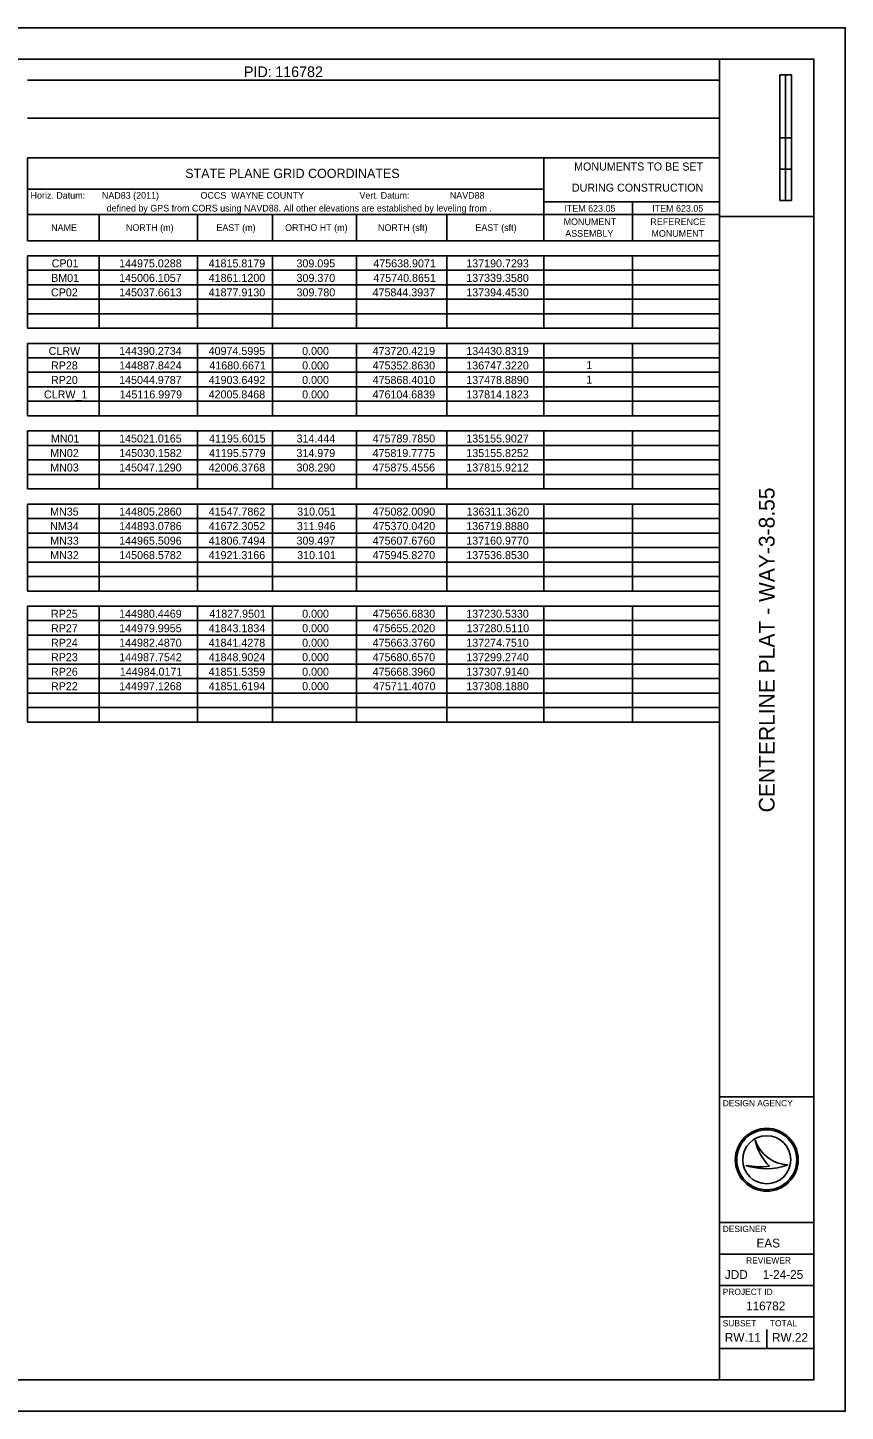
# Model space of a CAD drawing. Extents: x 0 to 34, y 0 to 22.
# Drawn here: x 21 to 34, y 0 to 22 of the extents above; entities that cross this region are included whole.
import ezdxf

# ---------------------------------------------------------------- set-up
doc = ezdxf.new("R2010")
doc.units = 0
for name, color, linetype in [('SH_Border', 7, 'Continuous'), ('SH_Cut_Line', 7, 'Continuous'), ('SH_Data', 7, 'Continuous'), ('SH_Text', 7, 'Continuous')]:
    doc.layers.add(name, color=color, linetype=linetype)

msp = doc.modelspace()

# ---------------------------------------------------------------- linework, layer by layer
at = {"layer": 'SH_Border'}
for p, q in [((32, 0.5), (32, 21.5)), ((32, 19), (33.5, 19)), ((32, 5), (33.5, 5)), ((32, 3), (33.5, 3)), ((32, 2.5), (33.5, 2.5)), ((32, 2), (33.5, 2)), ((32, 1.5), (33.5, 1.5)), ((32, 1), (33.5, 1))]:
    msp.add_line(p, q, dxfattribs=at)
msp.add_lwpolyline([(1.5, 21.5), (33.5, 21.5), (33.5, 0.5), (1.5, 0.5)], close=True, dxfattribs=at)
at = {"layer": 'SH_Cut_Line'}
msp.add_lwpolyline([(0, 0), (34, 0), (34, 22), (0, 22)], close=True, dxfattribs=at)
at = {"layer": 'SH_Data'}
for p, q in [((32.957, 19.25), (32.957, 21.25)), ((33.144, 21.25), (32.957, 21.25)), ((32.957, 20.25), (32.957, 21.25)), ((32.957, 21.25), (33.05, 21.25)), ((33.05, 21.25), (33.051, 21.25)), ((33.051, 21.25), (33.051, 20.25)), ((33.144, 21.25), (33.144, 19.25)), ((33.051, 20.25), (32.957, 20.25)), ((33.143, 20.25), (33.05, 20.25)), ((33.05, 20.25), (33.05, 19.75)), ((33.143, 19.75), (33.143, 20.25)), ((33.05, 19.75), (32.957, 19.75)), ((32.957, 19.75), (32.957, 19.25)), ((33.05, 19.75), (33.143, 19.75)), ((33.05, 19.25), (33.05, 19.75)), ((33.144, 19.25), (32.957, 19.25)), ((32.957, 19.25), (33.05, 19.25)), ((32.567, 4.31), (32.567, 4.31)), ((32.75, 4), (32.75, 4)), ((32.417, 3.91), (32.417, 3.91)), ((33.087, 3.919), (33.087, 3.919)), ((32.75, 1), (32.75, 1.3))]:
    msp.add_line(p, q, dxfattribs=at)
for radius in [0.5, 0.477, 0.477, 0.382]:
    msp.add_circle((32.75, 4), radius, dxfattribs=at)
for centre, radius, start, end in [((33.116, 4.498), 0.58, 198.9257, 198.9319), ((33.347, 4.47), 0.796, 191.6379, 191.6421), ((33.116, 4.498), 0.58, 198.9319, 267.1657), ((33.347, 4.47), 0.796, 191.6421, 226.0947), ((32.739, 4.87), 1.013, 251.4576, 290.0832), ((32.648, 5.154), 1.266, 259.4964, 259.4995), ((32.739, 4.87), 1.013, 251.4527, 251.4576), ((32.648, 5.154), 1.266, 259.4995, 276.6672)]:
    msp.add_arc(centre, radius, start, end, dxfattribs=at)
at = {"layer": 'SH_Text'}
for p, q in [((20.997, 21.168), (22.132, 21.168)), ((22.132, 21.168), (32, 21.168)), ((32, 21.168), (32, 19.932)), ((20.997, 20.559), (22.132, 20.559)), ((22.132, 20.559), (32, 20.559)), ((20.997, 19.932), (22.132, 19.932)), ((20.997, 19.932), (20.997, 19.028)), ((22.132, 19.932), (32, 19.932)), ((29.205, 19.932), (29.205, 19.028)), ((32, 19.932), (32, 19.028)), ((20.997, 19.434), (22.132, 19.434)), ((22.132, 19.434), (29.205, 19.434)), ((29.205, 19.231), (32, 19.231)), ((30.617, 19.231), (30.617, 19.028)), ((20.997, 19.028), (22.132, 19.028)), ((20.997, 19.028), (20.997, 18.613)), ((22.132, 19.028), (32, 19.028)), ((22.132, 19.028), (22.132, 18.613)), ((23.699, 19.028), (23.699, 18.613)), ((24.889, 19.028), (24.889, 18.613)), ((26.226, 19.028), (26.226, 18.613)), ((27.665, 19.028), (27.665, 18.613)), ((29.205, 19.028), (29.205, 18.613)), ((30.617, 19.028), (30.617, 18.613)), ((32, 19.028), (32, 17.451)), ((20.997, 18.613), (22.132, 18.613)), ((22.132, 18.613), (32, 18.613)), ((20.997, 18.373), (22.132, 18.373)), ((20.997, 18.373), (20.997, 17.451)), ((22.132, 18.373), (32, 18.373)), ((22.132, 18.373), (22.132, 17.451)), ((23.699, 18.373), (23.699, 17.451)), ((24.889, 18.373), (24.889, 17.451)), ((26.226, 18.373), (26.226, 17.451)), ((27.665, 18.373), (27.665, 17.451)), ((29.205, 18.373), (29.205, 17.451)), ((30.617, 18.373), (30.617, 17.451)), ((20.997, 18.143), (22.132, 18.143)), ((22.132, 18.143), (32, 18.143)), ((20.997, 17.912), (22.132, 17.912)), ((22.132, 17.912), (32, 17.912)), ((20.997, 17.682), (22.132, 17.682)), ((22.132, 17.682), (32, 17.682)), ((20.997, 17.451), (22.132, 17.451)), ((20.997, 17.451), (20.997, 17.221)), ((22.132, 17.451), (32, 17.451)), ((22.132, 17.451), (22.132, 17.221)), ((23.699, 17.451), (23.699, 17.221)), ((24.889, 17.451), (24.889, 17.221)), ((26.226, 17.451), (26.226, 17.221)), ((27.665, 17.451), (27.665, 17.221)), ((29.205, 17.451), (29.205, 17.221)), ((30.617, 17.451), (30.617, 17.221)), ((32, 17.451), (32, 16.981)), ((20.997, 17.221), (22.132, 17.221)), ((22.132, 17.221), (32, 17.221)), ((20.997, 16.981), (22.132, 16.981)), ((20.997, 16.981), (20.997, 15.828)), ((22.132, 16.981), (32, 16.981)), ((22.132, 16.981), (22.132, 15.828)), ((23.699, 16.981), (23.699, 15.828)), ((24.889, 16.981), (24.889, 15.828)), ((26.226, 16.981), (26.226, 15.828)), ((27.665, 16.981), (27.665, 15.828)), ((29.205, 16.981), (29.205, 15.828)), ((30.617, 16.981), (30.617, 15.828)), ((32, 16.981), (32, 13.504)), ((20.997, 16.75), (22.132, 16.75)), ((22.132, 16.75), (32, 16.75)), ((20.997, 16.52), (22.132, 16.52)), ((22.132, 16.52), (32, 16.52)), ((20.997, 16.289), (22.132, 16.289)), ((22.132, 16.289), (32, 16.289)), ((20.997, 16.059), (22.132, 16.059)), ((22.132, 16.059), (32, 16.059)), ((20.997, 15.828), (22.132, 15.828)), ((22.132, 15.828), (32, 15.828)), ((20.997, 15.588), (22.132, 15.588)), ((20.997, 15.588), (20.997, 14.666)), ((22.132, 15.588), (32, 15.588)), ((22.132, 15.588), (22.132, 14.666)), ((23.699, 15.588), (23.699, 14.666)), ((24.889, 15.588), (24.889, 14.666)), ((26.226, 15.588), (26.226, 14.666)), ((27.665, 15.588), (27.665, 14.666)), ((29.205, 15.588), (29.205, 14.666)), ((30.617, 15.588), (30.617, 14.666)), ((20.997, 15.358), (22.132, 15.358)), ((22.132, 15.358), (32, 15.358)), ((20.997, 15.127), (22.132, 15.127)), ((22.132, 15.127), (32, 15.127)), ((20.997, 14.896), (22.132, 14.896)), ((22.132, 14.896), (32, 14.896)), ((20.997, 14.666), (22.132, 14.666)), ((22.132, 14.666), (32, 14.666)), ((20.997, 14.426), (22.132, 14.426)), ((20.997, 14.426), (20.997, 13.504)), ((22.132, 14.426), (32, 14.426)), ((22.132, 14.426), (22.132, 13.504)), ((23.699, 14.426), (23.699, 13.504)), ((24.889, 14.426), (24.889, 13.504)), ((26.226, 14.426), (26.226, 13.504)), ((27.665, 14.426), (27.665, 13.504)), ((29.205, 14.426), (29.205, 13.504)), ((30.617, 14.426), (30.617, 13.504)), ((20.997, 14.195), (22.132, 14.195)), ((22.132, 14.195), (32, 14.195)), ((20.997, 13.965), (22.132, 13.965)), ((22.132, 13.965), (32, 13.965)), ((20.997, 13.734), (22.132, 13.734)), ((22.132, 13.734), (32, 13.734)), ((20.997, 13.504), (22.132, 13.504)), ((20.997, 13.504), (20.997, 13.043)), ((22.132, 13.504), (32, 13.504)), ((22.132, 13.504), (22.132, 13.043)), ((23.699, 13.504), (23.699, 13.043)), ((24.889, 13.504), (24.889, 13.043)), ((26.226, 13.504), (26.226, 13.043)), ((27.665, 13.504), (27.665, 13.043)), ((29.205, 13.504), (29.205, 13.043)), ((30.617, 13.504), (30.617, 13.043)), ((32, 13.504), (32, 12.803)), ((20.997, 13.273), (22.132, 13.273)), ((22.132, 13.273), (32, 13.273)), ((20.997, 13.043), (22.132, 13.043)), ((22.132, 13.043), (32, 13.043)), ((20.997, 12.803), (22.132, 12.803)), ((20.997, 12.803), (20.997, 10.958)), ((22.132, 12.803), (32, 12.803)), ((22.132, 12.803), (22.132, 10.958)), ((23.699, 12.803), (23.699, 10.958)), ((24.889, 12.803), (24.889, 10.958)), ((26.226, 12.803), (26.226, 10.958)), ((27.665, 12.803), (27.665, 10.958)), ((29.205, 12.803), (29.205, 10.958)), ((30.617, 12.803), (30.617, 10.958)), ((32, 12.803), (32, 10.958)), ((20.997, 12.572), (22.132, 12.572)), ((22.132, 12.572), (32, 12.572)), ((20.997, 12.342), (22.132, 12.342)), ((22.132, 12.342), (32, 12.342)), ((20.997, 12.111), (22.132, 12.111)), ((22.132, 12.111), (32, 12.111)), ((20.997, 11.881), (22.132, 11.881)), ((22.132, 11.881), (32, 11.881)), ((20.997, 11.65), (22.132, 11.65)), ((22.132, 11.65), (32, 11.65)), ((20.997, 11.419), (22.132, 11.419)), ((22.132, 11.419), (32, 11.419)), ((20.997, 11.189), (22.132, 11.189)), ((22.132, 11.189), (32, 11.189)), ((20.997, 10.958), (22.132, 10.958)), ((22.132, 10.958), (32, 10.958))]:
    msp.add_line(p, q, dxfattribs=at)

# ---------------------------------------------------------------- texts
at = {"layer": 'SH_Data'}
msp.add_text('CENTERLINE PLAT - WAY-3-8.55', height=0.25, rotation=90, dxfattribs=at).set_placement((32.875, 9.524))
for s, height, p in [('DESIGN AGENCY', 0.1, (32.05, 4.85)), ('DESIGNER', 0.1, (32.05, 2.85)), ('EAS', 0.14, (32.587, 2.605)), ('REVIEWER', 0.1, (32.422, 2.35)), ('JDD', 0.14, (32.084, 2.105)), ('1-24-25', 0.14, (32.685, 2.105)), ('PROJECT ID', 0.1, (32.05, 1.85)), ('116782', 0.14, (32.421, 1.605)), ('SUBSET', 0.1, (32.05, 1.35)), ('TOTAL', 0.1, (32.8, 1.35)), ('RW.11', 0.14, (32.084, 1.105)), ('RW.22', 0.14, (32.834, 1.105))]:
    msp.add_text(s, height=height, dxfattribs=at).set_placement(p)
at = {"layer": 'SH_Text'}
for s, height, p in [('PID:', 0.1697, (24.437, 21.214)), ('116782', 0.1697, (24.935, 21.214)), ('  MONUMENTS TO BE SET', 0.12728, (29.592, 19.729)), ('STATE PLANE GRID COORDINATES', 0.14849, (23.503, 19.609)), ('Horiz. Datum:', 0.10606, (21.043, 19.28)), ('NAD83 (2011)', 0.10606, (22.178, 19.28)), ('OCCS  WAYNE COUNTY', 0.10606, (23.746, 19.28)), ('Vert. Datum:', 0.10606, (26.273, 19.28)), ('NAVD88', 0.1061, (27.711, 19.28)), (' DURING CONSTRUCTION', 0.12728, (29.604, 19.393)), (' defined by GPS from CORS using NAVD88. All other elevations are established by leveling from .', 0.10606, (22.214, 19.077)), ('ITEM 623.05', 0.10606, (29.532, 19.074)), ('ITEM 623.05', 0.10606, (30.929, 19.074)), ('MONUMENT ', 0.1061, (29.52, 18.861)), ('REFERENCE ', 0.1061, (30.9, 18.861)), ('NAME', 0.1061, (21.371, 18.768)), ('NORTH (m)', 0.1061, (22.56, 18.768)), ('EAST (m)', 0.1061, (23.998, 18.768)), ('ORTHO HT (m)', 0.10606, (25.091, 18.768)), ('NORTH (sft)', 0.10606, (26.568, 18.768)), ('EAST (sft)', 0.1061, (28.117, 18.768)), ('ASSEMBLY', 0.1061, (29.546, 18.675)), ('MONUMENT', 0.1061, (30.917, 18.675)), ('CP01', 0.1273, (21.379, 18.189)), ('144975.0288', 0.12728, (22.452, 18.189)), ('41815.8179', 0.1273, (23.875, 18.189)), ('309.095', 0.1273, (25.272, 18.189)), ('475638.9071', 0.12728, (26.494, 18.189)), ('137190.7293', 0.12728, (27.972, 18.189)), ('BM01', 0.1273, (21.37, 17.958)), ('145006.1057', 0.12728, (22.452, 17.958)), ('41861.1200', 0.1273, (23.876, 17.958)), ('309.370', 0.1273, (25.273, 17.958)), ('475740.8651', 0.12728, (26.494, 17.958)), ('137339.3580', 0.12728, (27.972, 17.958)), ('CP02', 0.1273, (21.368, 17.728)), ('145037.6613', 0.12728, (22.452, 17.728)), ('41877.9130', 0.1273, (23.876, 17.728)), ('309.780', 0.1273, (25.273, 17.728)), ('475844.3937', 0.12728, (26.482, 17.728)), ('137394.4530', 0.12728, (27.972, 17.728)), ('CLRW', 0.1273, (21.331, 16.796)), ('144390.2734', 0.12728, (22.452, 16.796)), ('40974.5995', 0.1273, (23.875, 16.796)), ('0.000', 0.1273, (25.362, 16.796)), ('473720.4219', 0.12728, (26.482, 16.796)), ('134430.8319', 0.12728, (27.972, 16.796)), ('RP28', 0.1273, (21.368, 16.566)), ('144887.8424', 0.12728, (22.452, 16.566)), ('41680.6671', 0.1273, (23.886, 16.566)), ('0.000', 0.1273, (25.362, 16.566)), ('475352.8630', 0.12728, (26.483, 16.566)), ('136747.3220', 0.12728, (27.972, 16.566)), ('1', 0.127, (29.881, 16.571)), ('RP20', 0.1273, (21.368, 16.335)), ('145044.9787', 0.12728, (22.452, 16.335)), ('41903.6492', 0.1273, (23.876, 16.335)), ('0.000', 0.1273, (25.362, 16.335)), ('475868.4010', 0.12728, (26.483, 16.335)), ('137478.8890', 0.12728, (27.972, 16.335)), ('1', 0.127, (29.881, 16.341)), ('CLRW_1', 0.1273, (21.256, 16.105)), ('145116.9979', 0.12728, (22.458, 16.105)), ('42005.8468', 0.1273, (23.875, 16.105)), ('0.000', 0.1273, (25.362, 16.105)), ('476104.6839', 0.12728, (26.482, 16.105)), ('137814.1823', 0.12728, (27.972, 16.105)), ('MN01', 0.1273, (21.366, 15.404)), ('145021.0165', 0.12728, (22.452, 15.404)), ('41195.6015', 0.1273, (23.881, 15.404)), ('314.444', 0.1273, (25.273, 15.404)), ('475789.7850', 0.12728, (26.483, 15.404)), ('135155.9027', 0.12728, (27.972, 15.404)), ('MN02', 0.1273, (21.355, 15.173)), ('145030.1582', 0.12728, (22.453, 15.173)), ('41195.5779', 0.1273, (23.881, 15.173)), ('314.979', 0.1273, (25.272, 15.173)), ('475819.7775', 0.12728, (26.482, 15.173)), ('135155.8252', 0.12728, (27.973, 15.173)), ('MN03', 0.1273, (21.355, 14.943)), ('145047.1290', 0.12728, (22.452, 14.943)), ('42006.3768', 0.1273, (23.875, 14.943)), ('308.290', 0.1273, (25.273, 14.943)), ('475875.4556', 0.12728, (26.482, 14.943)), ('137815.9212', 0.12728, (27.973, 14.943)), ('MN35', 0.1273, (21.354, 14.242)), ('144805.2860', 0.12728, (22.452, 14.242)), ('41547.7862', 0.1273, (23.876, 14.242)), ('310.051', 0.1273, (25.283, 14.242)), ('475082.0090', 0.12728, (26.483, 14.242)), ('136311.3620', 0.12728, (27.978, 14.242)), ('NM34', 0.1273, (21.355, 14.011)), ('144893.0786', 0.12728, (22.452, 14.011)), ('41672.3052', 0.1273, (23.876, 14.011)), ('311.946', 0.1273, (25.278, 14.011)), ('475370.0420', 0.12728, (26.483, 14.011)), ('136719.8880', 0.12728, (27.972, 14.011)), ('MN33', 0.1273, (21.355, 13.78)), ('144965.5096', 0.12728, (22.452, 13.78)), ('41806.7494', 0.1273, (23.876, 13.78)), ('309.497', 0.1273, (25.272, 13.78)), ('475607.6760', 0.12728, (26.483, 13.78)), ('137160.9770', 0.12728, (27.972, 13.78)), ('MN32', 0.1273, (21.355, 13.55)), ('145068.5782', 0.12728, (22.453, 13.55)), ('41921.3166', 0.1273, (23.875, 13.55)), ('310.101', 0.1273, (25.283, 13.55)), ('475945.8270', 0.12728, (26.483, 13.55)), ('137536.8530', 0.12728, (27.972, 13.55)), ('RP25', 0.1273, (21.367, 12.618)), ('144980.4469', 0.12728, (22.452, 12.618)), ('41827.9501', 0.1273, (23.886, 12.618)), ('0.000', 0.1273, (25.362, 12.618)), ('475656.6830', 0.12728, (26.483, 12.618)), ('137230.5330', 0.12728, (27.972, 12.618)), ('RP27', 0.1273, (21.368, 12.388)), ('144979.9955', 0.12728, (22.452, 12.388)), ('41843.1834', 0.1273, (23.876, 12.388)), ('0.000', 0.1273, (25.362, 12.388)), ('475655.2020', 0.12728, (26.483, 12.388)), ('137280.5110', 0.12728, (27.978, 12.388)), ('RP24', 0.1273, (21.368, 12.157)), ('144982.4870', 0.12728, (22.452, 12.157)), ('41841.4278', 0.1273, (23.875, 12.157)), ('0.000', 0.1273, (25.362, 12.157)), ('475663.3760', 0.12728, (26.483, 12.157)), ('137274.7510', 0.12728, (27.972, 12.157)), ('RP23', 0.1273, (21.368, 11.927)), ('144987.7542', 0.12728, (22.453, 11.927)), ('41848.9024', 0.1273, (23.876, 11.927)), ('0.000', 0.1273, (25.362, 11.927)), ('475680.6570', 0.12728, (26.483, 11.927)), ('137299.2740', 0.12728, (27.972, 11.927)), ('RP26', 0.1273, (21.368, 11.696)), ('144984.0171', 0.12728, (22.463, 11.696)), ('41851.5359', 0.1273, (23.875, 11.696)), ('0.000', 0.1273, (25.362, 11.696)), ('475668.3960', 0.12728, (26.483, 11.696)), ('137307.9140', 0.12728, (27.972, 11.696)), ('RP22', 0.1273, (21.368, 11.466)), ('144997.1268', 0.12728, (22.452, 11.466)), ('41851.6194', 0.1273, (23.876, 11.466)), ('0.000', 0.1273, (25.362, 11.466)), ('475711.4070', 0.12728, (26.489, 11.466)), ('137308.1880', 0.12728, (27.972, 11.466))]:
    msp.add_text(s, height=height, dxfattribs=at).set_placement(p)

doc.saveas('drawing.dxf')
